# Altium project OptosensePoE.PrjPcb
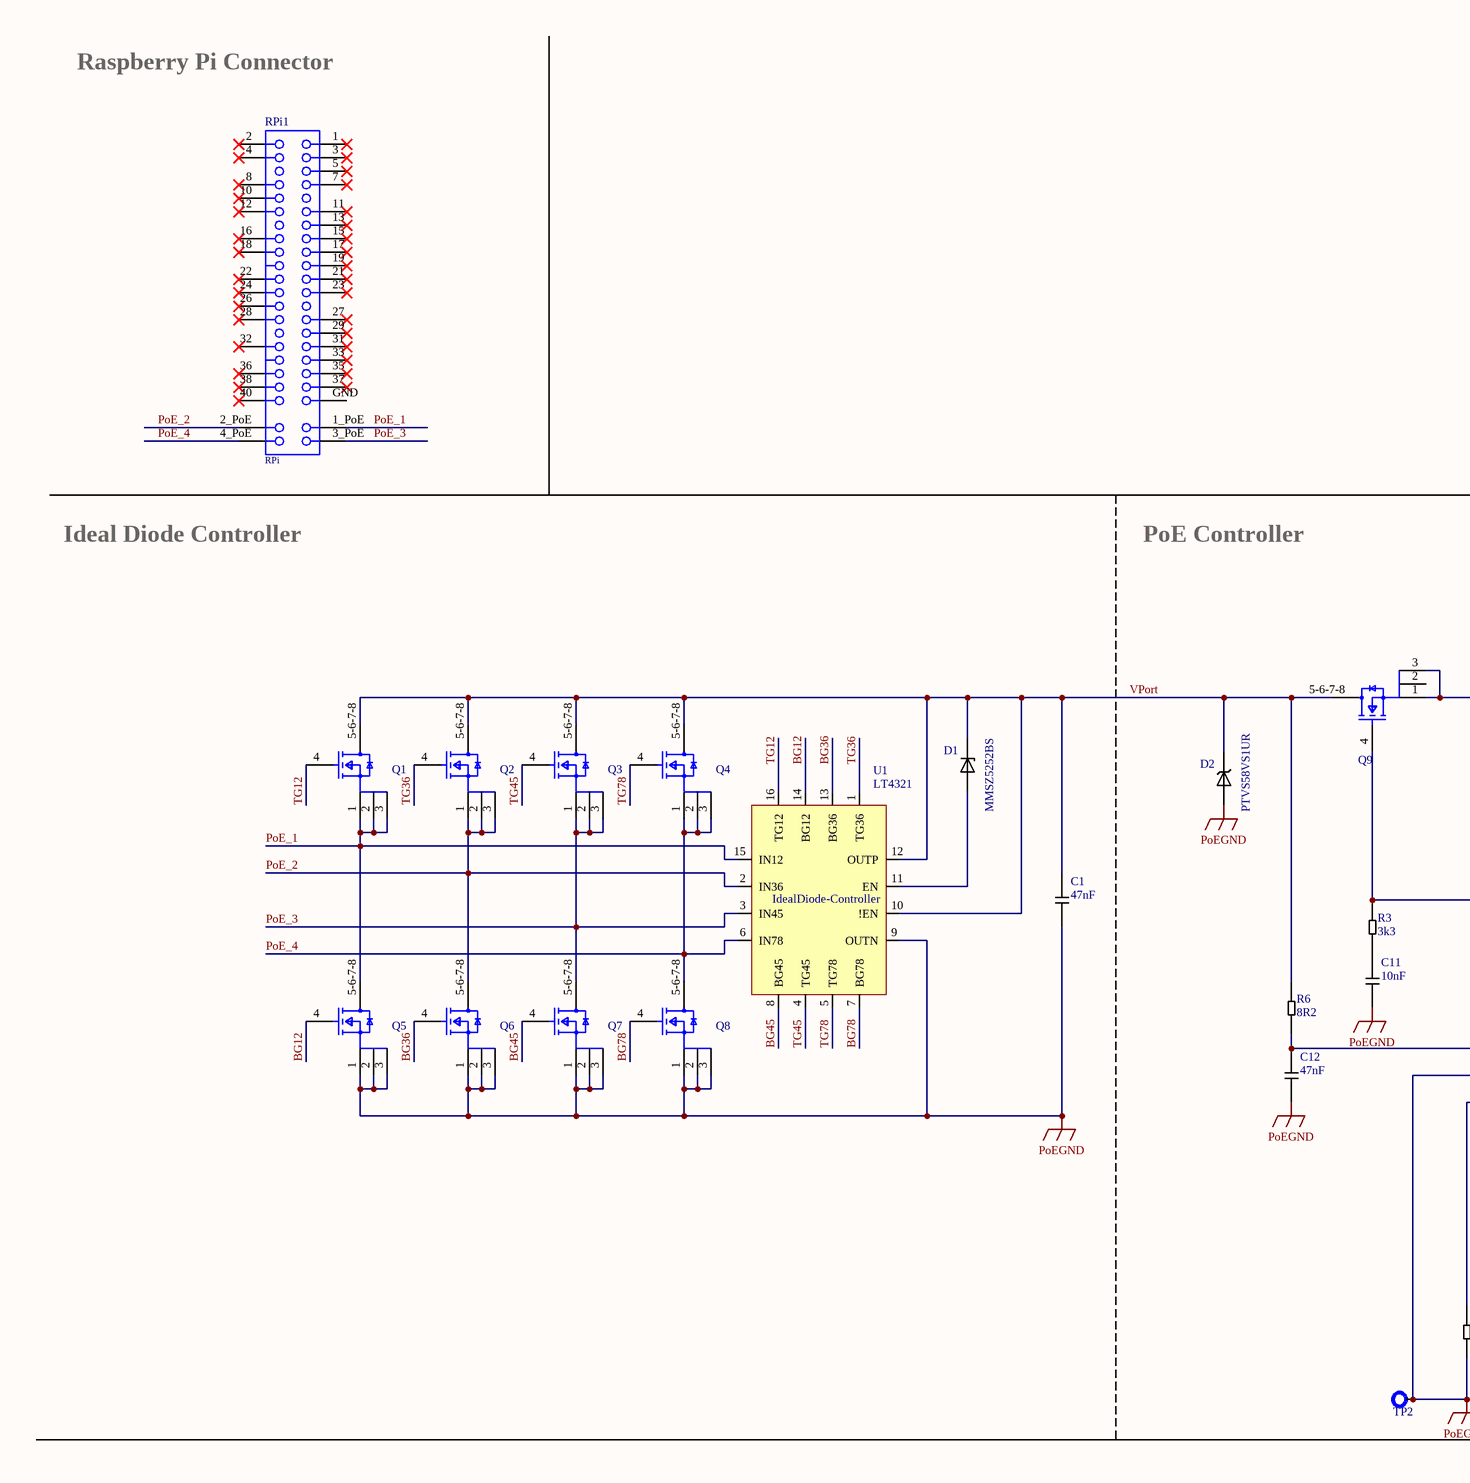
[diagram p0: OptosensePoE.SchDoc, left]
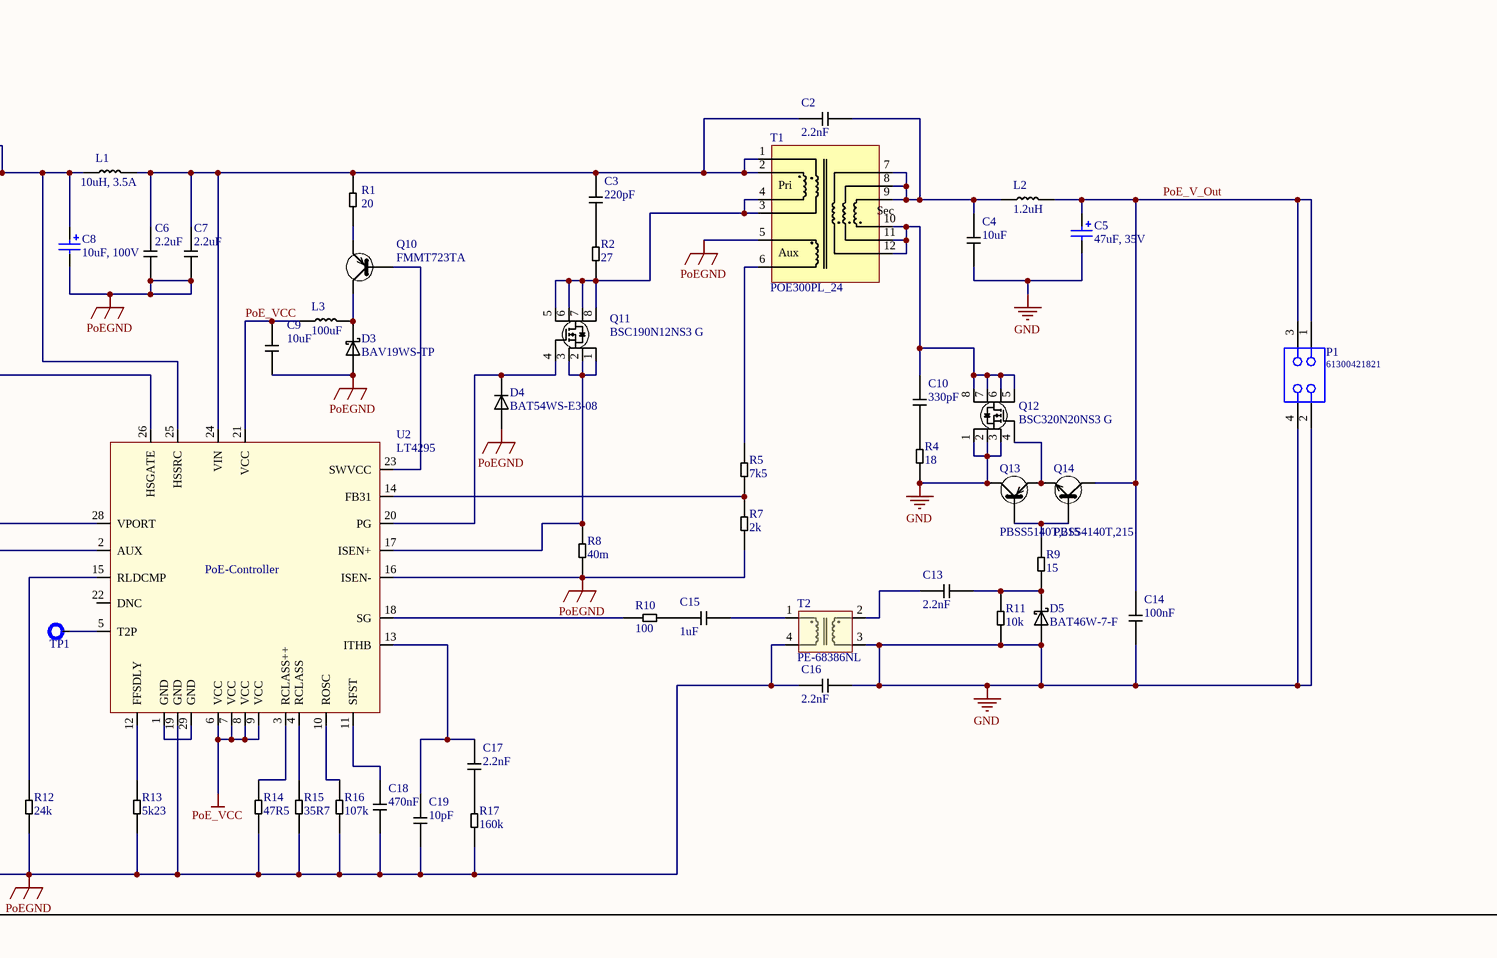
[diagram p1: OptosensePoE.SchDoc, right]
1 sheet, 66 parts. Net scope: global (net labels, ports and power ports of the same name join across sheets).
Board file: OptosensePoE.PcbDoc

## Sheet OptosensePoE.SchDoc
size A2

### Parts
C1  47nF  [C_0603]
C2  2.2nF  [C_CK45]
C3  220pF  [C_1206]
C4  10uF  [C_1206]
C5  47uF, 35V  [WCAP-ASLI_D6.3H5.5]
C6  2.2uF  [C_1210]
C7  2.2uF  [C_1210]
C8  10uF, 100V  [CAPAE830X1080N]
C9  10uF  [C_1206]
C10  330pF  [C_1206]
C11  10nF  [C_0603]
C12  47nF  [C_0603]
C13  2.2nF  [C_0603]
C14  100nF  [C_0805]
C15  1uF  [C_0603]
C16  2.2nF  [C_CK45]
C17  2.2nF  [C_0603]
C18  470nF  [C_0603]
C19  10pF  [C_0603]
D1  MMSZ5252BS  [SOD323]
D2  PTVS58VS1UR  [D_SOD123]
D3  BAV19WS-TP  [D_SOD323]
D4  BAT54WS-E3-08  [D_SOD323]
D5  BAT46W-7-F  [D_SOD123]
L1  10uH, 3.5A  [WE-HCI_7050]
L2  1.2uH  [L_XAL5030]
L3  100uF  [L_6028]
P1  61300421821  [61300421821]
Q1  SI7322ADN-T1-GE3  [Vishay_S16-2667-SINGLE_MFG]  (value not drawn)
Q2  SI7322ADN-T1-GE3  [Vishay_S16-2667-SINGLE_MFG]  (value not drawn)
Q3  SI7322ADN-T1-GE3  [Vishay_S16-2667-SINGLE_MFG]  (value not drawn)
Q4  SI7322ADN-T1-GE3  [Vishay_S16-2667-SINGLE_MFG]  (value not drawn)
Q5  SI7322ADN-T1-GE3  [Vishay_S16-2667-SINGLE_MFG]  (value not drawn)
Q6  SI7322ADN-T1-GE3  [Vishay_S16-2667-SINGLE_MFG]  (value not drawn)
Q7  SI7322ADN-T1-GE3  [Vishay_S16-2667-SINGLE_MFG]  (value not drawn)
Q8  SI7322ADN-T1-GE3  [Vishay_S16-2667-SINGLE_MFG]  (value not drawn)
Q9  SI7322ADN-T1-GE3  [Vishay_S16-2667-SINGLE_MFG]  (value not drawn)
Q10  FMMT723TA  [SOT-23-3]
Q11  BSC190N12NS3 G  [PG-TDSON-8]
Q12  BSC320N20NS3 G  [PG-TDSON-8]
Q13  PBSS5140T,215  [SOT-23-3]
Q14  PBSS4140T,215  [SOT-23-3]
R1  20  [R_0805]
R2  27  [R_0805]
R3  3k3  [R_0603]
R4  18  [R_2512]
R5  7k5  [R_0805]
R6  8R2  [R_0805]
R7  2k  [R_0805]
R8  40m  [R_0805]
R9  15  [R_0603]
R10  100  [R_0603]
R11  10k  [R_0603]
R12  24k  [R_0603]
R13  5k23  [R_0603]
R14  47R5  [R_0603]
R15  35R7  [R_0603]
R16  107k  [R_0603]
R17  160k  [R_0603]
RPi1  RPi  [RPi - THT Hybrid - NoneHeader]
T1  POE300PL_24  [Transformer_Coilcraft_POE300]
T2  PE-68386NL  [T_PE-68386NL]
TP1  TP  [Testpoint]  (value not drawn)
TP2  TP  [Testpoint]  (value not drawn)
U1  LT4321  [IC_QFN_16_Plastic]
U2  LT4295  [IC_QNF_28_PLASTIC]

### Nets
GND: C4.1 C5.2(N) C14.1 C16.2 D5.A P1.2 P1.4 Q12.1(S) Q12.2(S) Q12.3(S) Q13.C R4.1 R11.1 T2.3
PoE_VCC: C9.1 L3.1 U2.6(VCC) U2.7(VCC) U2.8(VCC) U2.9(VCC) U2.21(VCC)
PoEGND: C1.1 C6.1 C7.1 C8.2(N) C9.2 C11.1 C12.1 C16.1 C18.1 C19.1 D2.A D3.A D4.A Q5.1(S) Q5.2(S) Q5.3(S) Q6.1(S) Q6.2(S) Q6.3(S) Q7.1(S) Q7.2(S) Q7.3(S) Q8.1(S) Q8.2(S) Q8.3(S) R7.1 R8.1 R12.1 R13.1 R14.1 R15.1 R16.1 R17.1 T1.5 T2.4 TP2.1 U1.9(OUTN) U2.2(AUX) U2.16(ISEN-) U2.19(GND)
BG12: Q5.4(G) U1.14(BG12)
BG36: Q6.4(G) U1.13(BG36)
BG45: Q7.4(G) U1.8(BG45)
BG78: Q8.4(G) U1.7(BG78)
PoE_1: Q1.1(S) Q1.2(S) Q1.3(S) Q5.5-6-7-8(D) RPi1.1_PoE U1.15(IN12)
PoE_2: Q2.1(S) Q2.2(S) Q2.3(S) Q6.5-6-7-8(D) RPi1.2_PoE U1.2(IN36)
PoE_3: Q3.1(S) Q3.2(S) Q3.3(S) Q7.5-6-7-8(D) RPi1.3_PoE U1.3(IN45)
PoE_4: Q4.1(S) Q4.2(S) Q4.3(S) Q8.5-6-7-8(D) RPi1.4_PoE U1.6(IN78)
PoE_V_Out: C5.1(P) C14.2 L2.2 P1.1 P1.3 Q14.C
TG12: Q1.4(G) U1.16(TG12)
TG36: Q2.4(G) U1.1(TG36)
TG45: Q3.4(G) U1.4(TG45)
TG78: Q4.4(G) U1.5(TG78)
VPort: C1.2 D1.K D2.K Q1.5-6-7-8(D) Q2.5-6-7-8(D) Q3.5-6-7-8(D) Q4.5-6-7-8(D) Q9.5-6-7-8(D) R6.2 U1.10(!EN) U1.12(OUTP)
NetC2_1: C2.1 C3.2 C6.2 C7.2 L1.2 R1.1 T1.1 T1.2 U2.24(VIN)
NetC2_2: C2.2 C4.2 L2.1 T1.7 T1.8 T1.9
NetC3_1: C3.1 R2.2
NetC8_1: C8.1(P) L1.1 Q9.1(S) Q9.3(S) U2.25(HSSRC)
NetC10_1: C10.1 R4.2
NetC10_2: C10.2 Q12.5 Q12.6 Q12.7 Q12.8 T1.10 T1.11 T1.12
NetC11_2: C11.2 R3.1
NetC12_2: C12.2 R6.1 U2.28(VPORT)
NetC13_1: C13.1 T2.2
NetC13_2: C13.2 D5.K R9.1 R11.2
NetC15_1: C15.1 R10.2
NetC15_2: C15.2 T2.1
NetC17_1: C17.1 R17.2
NetC17_2: C17.2 C19.2 U2.13(ITHB)
NetC18_2: C18.2 U2.11(SFST)
NetD1_A: D1.A U1.11(EN)
NetD3_K: D3.K L3.2 Q10.C
NetD4_K: D4.K Q11.4 U2.20(PG)
NetQ9_4: Q9.4(G) R3.2 U2.26(HSGATE)
NetQ10_B: Q10.B U2.23(SWVCC)
NetQ10_E: Q10.E R1.2
NetQ11_1: Q11.1(S) Q11.2(S) Q11.3(S) R8.2 U2.17(ISEN+)
NetQ11_5: Q11.5 Q11.6 Q11.7 Q11.8 R2.1 T1.3 T1.4
NetQ12_4: Q12.4 Q13.E Q14.E
NetQ13_B: Q13.B Q14.B R9.2
NetR5_1: R5.1 R7.2 U2.14(FB31)
NetR5_2: R5.2 T1.6
NetR10_1: R10.1 U2.18(SG)
NetR12_2: R12.2 U2.15(RLDCMP)
NetR13_2: R13.2 U2.12(FFSDLY)
NetR14_2: R14.2 U2.3(RCLASS++)
NetR15_2: R15.2 U2.4(RCLASS)
NetR16_2: R16.2 U2.10(ROSC)
NetTP1_1: TP1.1 U2.5(T2P)
NetU2_1: U2.1(GND) U2.29(GND)

Not connected (* = marked no-connect by the designer): Q9 2(S); RPi1 1* 2* 3* 4* 5* 7* 8* 10* 11* 12* 13* 15* 16* 17* 18* 19* 21* 22* 23* 24* 26* 27* 28* 29* 31* 32* 33* 35* 36* 37* 38* 40* GND; U2 22(DNC)

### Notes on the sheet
- Raspberry Pi Connector
- Ideal Diode Controller
- PoE Controller

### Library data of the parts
C1 C12 = C_47n_0603_100V_10%: 885012206118
C2 C16 = C_2n2_2kV_10%: CK45-B3DD222KYVNA
C3 = C_220p_1206_630V_5%: 1206N221J631CT
C4 = C_10u_1206_50V_10%: UMK316BBJ106KL-T
C5 = 865080543009: WCAP-ASLI Aluminum Electrolytic Capacitor, V-Chip, SMT, D6.3xH5.5mm, 47uF, 35V; Manufacturer: Wurth Elektronik; Technical Reference: ASED055470M035DVCTBB000; Ripple Current: 240mA; Capacitance Tolerance: +/-20%; Leakage Current: 16.45uA; Endurance: 2000h; Dissipation Factor: 14%; Rated Voltage: 35VDC
C6 C7 = C_2u2_1210_100V_10%: HMK325B7225KM-T
C8 = C_10uF_100V_Elko: EEE-2AA100P; Manufacturer Part Number: 865080543009; Manufacturer: Wurth Elektronik; Technical Reference: ASED055470M035DVCTBB000; Ripple Current: 240mA; Capacitance Tolerance: +/-20%; Leakage Current: 16.45uA; Endurance: 2000h; Dissipation Factor: 14%; Capacitance: 47uF; Rated Voltage: 35VDC
C9 = C_10u_1206_10V_10%: LMK316B7106KL-T
C10 = C_330p_1206_100V_5%: 885012008070
C11 = C_10n_0603_100V_10%: C1608X7R2A103K080AA
C13 = C_2n2_0603_50V_10%: 06035C222KAT4A
C14 = C_0u1_0805_50V_10%: 885012207098
C15 = C_1u_0603_25V_10%: TMK107B7105KA-T
C17 = C_3n3_0603_50V_100%: VJ0603Y332KXACW1BC
C18 = C_470n_0603_50V_10%: UMK107B7474KA-TR
C19 = C_10p_0603_50V_10%: 06035C100K4T4A
D1 = D_Zener_SOD-323: 24V_MMSZ5252BS
D2 = D_TVS_SOD123: TVS_58V_SOD123_PTVS58VS1UR
D3 = D_Schottky_SOD323_BAV19WS-TP
D4 = D_SOD323_BAT54WS-E3-08
D5 = D_Schottky_SOD123
L1 = 744314101: WE-HCI SMT Flat Wire High Current Inductor, size 7050, 10uH, 3.5A; Manufacturer: Wurth Elektronik; DC Resistance: 33mOhm; Material: Superflux; Self Resonant Frequency: 40MHz; Saturation Current: 4A; Rated Inductance: 7.5uH
L2 = L_1u2: XAL5030-122MEC
L3 = L_100u: NRS6028T101MMGJ
P1 = 61300421821: WR-PHD Socket Header, THT, pitch 2.54mm, Dual Row, Vertical, 4p; Manufacturer: Wurth Elektronik; Pin Number: 4; Rated Current: 3A; Working Voltage: 250VAC; Withstanding Voltage: 500VAC; Contact Resistance: 20mOhm
Q10 = Q_PNP-Transistor_FMMT723TA: PNP_FMMT723TA
Q11 = Q_N-Channel_MOSFET_PG-TDSON-8: N-Channel MOSFET
Q12 = Q_N-Channel_MOSFET_PG-TDSON-8_BSC320N20NS3 G
Q13 = Q_PNP-Transistor_PBSS5140T,215: PNP_PBSS5140T,215
Q14 = Q_NPN-Transistor_PBSS4140T,215
R1 = R_20_0805: CRCW080520R0JNEA
R2 = R_27_0805_5%_0W5: ERJ-P06J270V
R3 = R_3k3_0603_1%: CRCW06033K30FKEAC
R4 = R_18_2512_1%_1W: ERJ-1TNF18R0U
R5 = R_7k5_0805_1%: ERJ-P06F7501V
R6 = R_8R2_0805: CRCW08058R20JNEA
R7 = R_2k_1%_0W5: AC0805FR-7W2KL
R8 = R_40m_0805_0W5_1%: WSLP0805R0400FEA
R9 = R_15_0603_1%: CRCW060315R0FKEB
R10 = R_100_0603_1%: CRCW0603100RFKEAC
R11 = R_10k_0603_1%: CRCW060310K0FKEA
R12 = R_24k_0603_1%: CRCW060324K0FKEA
R13 = R_5k23_0603_1%: CRCW06035K23FKEA
R14 = R_47R5_0603
R15 = R_35R7_0603
R16 = R_107k_0603_1%: CRCW0603107KFKEA
R17 = R_160k_0603_1%: CRCW0603160KFKEA
RPi1 = RPi: WR-PHD Socket Header, SMT, pitch 2.54mm, Dual Row, Vertical, 40pin; Part Number: 61004021821; Pin Number: 40; Gender: Female; Rated Current: 3A; Working Voltage: 250VAC; Withstanding Voltage: 600VAC; Contact Resistance: 20mOhm
T1 = T_Transformer_PoE30W_24V: Transformer_PoE_24V_30W
T2 = T_Transformer_Gatedrive_PE-68386NL: Transformer_Gatedrive_PE-68386NL
TP1 TP2 = Testpoint
U1 = IC_LT4321: LT4321IUF
U2 = IC_LT4295

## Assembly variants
25W: not fitted C19 R3; alternate parts T4 -> T_Transformer_PoE30W_24V, L1 -> 744314101
51W: alternate parts L1 -> 744314650, R? -> R_12k3_0402, R2 -> R_150R_0603, R? -> R_36k_0402_1%, C? -> C_330p_0402_50V_10%, C? -> C_10n_0402_25V_10%, R? -> R_22k_0402, C? -> C_22u_Elko_1, T? -> T_Transformer_POE51Q-24ED_POE300, R? -> R_15m_0805, T? -> T_Transformer_PoE30W_24V_POE51Q, C? -> C_22u_Elko_1, L? -> L_6u5, T? -> T_Transformer_POE51Q-24ED, T? -> T_Transformer_POE51Q-24ED, R? -> R_12k1_0805_1%, C? -> C_22uF_100V_Elko, R? -> R_36k_0603_1%, R? -> R_22k_0603_1%, C? -> C_330p_0603_50V_10%, C? -> C_10n_0603_50V_10%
